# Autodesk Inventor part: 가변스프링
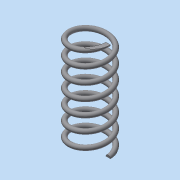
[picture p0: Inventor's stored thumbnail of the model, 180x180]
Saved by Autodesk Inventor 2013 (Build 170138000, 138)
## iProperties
Created: 2018-11
Part Number: 가변스프링
Material: 일반
Document SubType Name: Modeling
Designer: dgall
Density: 1 g/cm^3
Author: dgall
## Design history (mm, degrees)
sketch "스케치1"
  geometry: L1 (0, 0)-(8, 0); L2 (8, 0)-(8, 43.5); L3 (8, 43.5)-(0, 43.5); L4 (0, 43.5)-(0, 0); C1 r 1 at (8, 0)
  constraints: 8 end point, 2 parallel, 1 centre point, 1 coincident, 1 horizontal, 1 perpendicular
  dimensions: "d0" = 43.5 distance of L3.end L1.start (derived); "d1" = 16 diameter of L2 L4; "d2" = 2 diameter of C1
feature "코일1" pitch "d3" = 10; turns "d5" = 7; dims "d4" = 43.5 (= d0), "d6" = 0, angle "d7" = 90 deg, angle "d8" = 90 deg, "d9" = 0, "d10" = 0
node "작업 평면1"
node "작업 평면2"
feature "분할1"
feature "분할2"
node "솔리드1"
